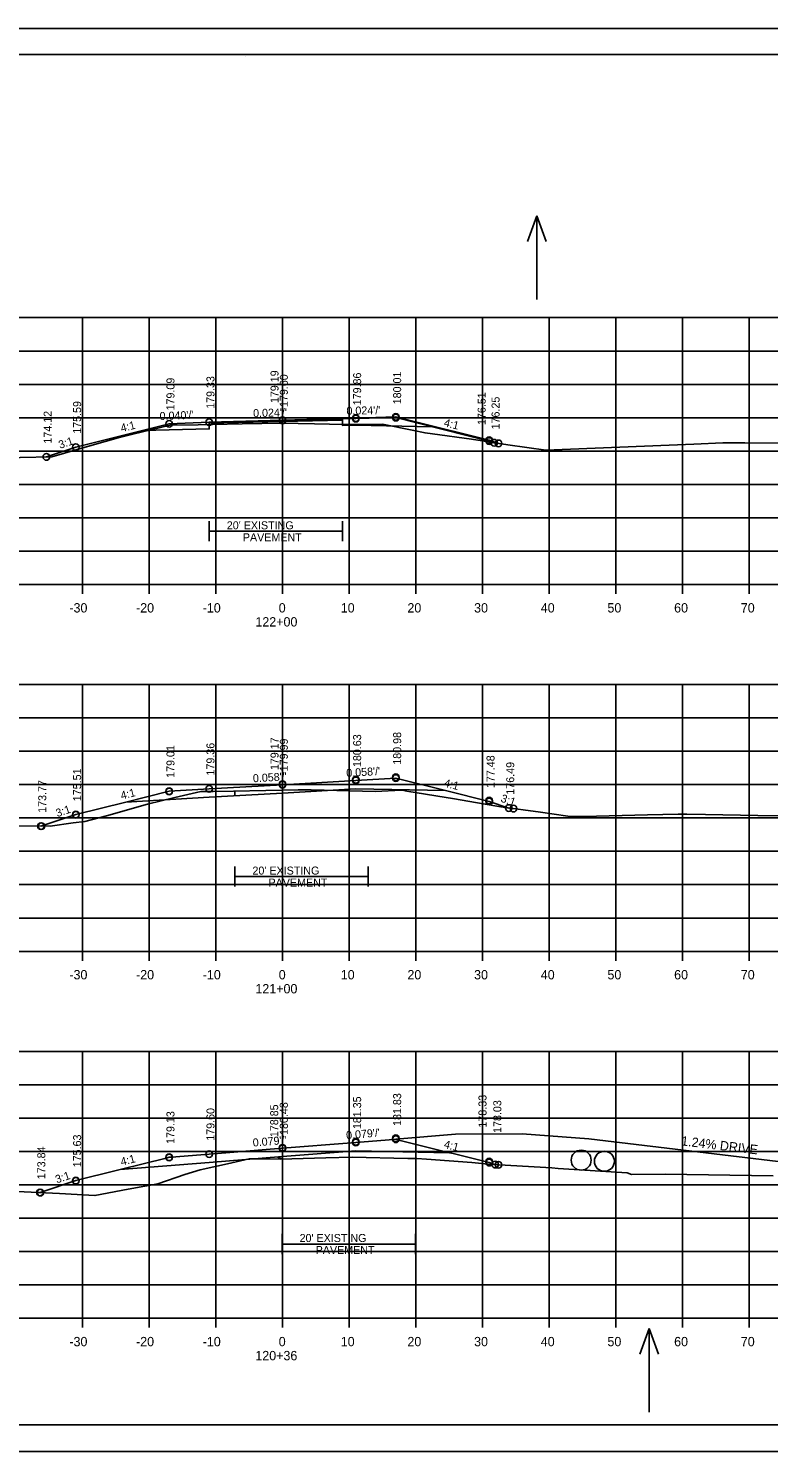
# Model space of a CAD drawing. Extents: x 915787 to 919910, y 133456 to 136717.
# Drawn here: x 916375.9 to 916486.9, y 136016.1 to 136229.4 of the extents above; entities that cross this region are included whole.
import ezdxf

# ---------------------------------------------------------------- set-up
doc = ezdxf.new("R2010")
doc.units = 0
for name, color, linetype in [('R_Alt Surface', 7, 'Continuous'), ('R_Axis', 7, 'Continuous'), ('R_Axis Annot', 7, 'Continuous'), ('R_Border', 7, 'Continuous'), ('R_Drive', 7, 'Continuous'), ('R_Exist Surface', 7, 'Continuous'), ('R_Exist Surface Annot', 7, 'Continuous'), ('R_Fin Surface', 7, 'Continuous'), ('R_Grid', 7, 'Continuous'), ('R_No Plot', 7, 'Continuous'), ('R_Water', 7, 'Continuous'), ('R_Water Annot', 7, 'Continuous'), ('R_Xsect Elev', 7, 'Continuous'), ('R_Xsect Slope', 7, 'Continuous')]:
    doc.layers.add(name, color=color, linetype=linetype)

msp = doc.modelspace()

# ---------------------------------------------------------------- linework, layer by layer
at = {"layer": 'R_Alt Surface'}
msp.add_lwpolyline([(916378.56, 136165.19), (916382.97, 136166.66), (916396.18, 136169.96), (916396.97, 136170.16), (916402.97, 136170.4), (916413.97, 136170.71), (916424.97, 136171.02), (916430.97, 136171.19), (916433.72, 136170.51), (916444.97, 136167.69), (916446.37, 136167.23)], dxfattribs=at)
at = {"layer": 'R_Axis'}
for p, q in [((916273.98, 136146.07), (916553.98, 136146.07)), ((916383.98, 136144.67), (916383.98, 136146.07)), ((916393.98, 136144.67), (916393.98, 136146.07)), ((916403.98, 136144.67), (916403.98, 136146.07)), ((916413.98, 136144.67), (916413.98, 136146.07)), ((916423.98, 136144.67), (916423.98, 136146.07)), ((916433.98, 136144.67), (916433.98, 136146.07)), ((916443.98, 136144.67), (916443.98, 136146.07)), ((916453.98, 136144.67), (916453.98, 136146.07)), ((916463.98, 136144.67), (916463.98, 136146.07)), ((916473.98, 136144.67), (916473.98, 136146.07)), ((916483.98, 136144.67), (916483.98, 136146.07)), ((916273.98, 136091.07), (916553.98, 136091.07)), ((916383.98, 136089.67), (916383.98, 136091.07)), ((916393.98, 136089.67), (916393.98, 136091.07)), ((916403.98, 136089.67), (916403.98, 136091.07)), ((916413.98, 136089.67), (916413.98, 136091.07)), ((916423.98, 136089.67), (916423.98, 136091.07)), ((916433.98, 136089.67), (916433.98, 136091.07)), ((916443.98, 136089.67), (916443.98, 136091.07)), ((916453.98, 136089.67), (916453.98, 136091.07)), ((916463.98, 136089.67), (916463.98, 136091.07)), ((916473.98, 136089.67), (916473.98, 136091.07)), ((916483.98, 136089.67), (916483.98, 136091.07)), ((916273.98, 136036.07), (916553.98, 136036.07)), ((916383.98, 136034.67), (916383.98, 136036.07)), ((916393.98, 136034.67), (916393.98, 136036.07)), ((916403.98, 136034.67), (916403.98, 136036.07)), ((916413.98, 136034.67), (916413.98, 136036.07)), ((916423.98, 136034.67), (916423.98, 136036.07)), ((916433.98, 136034.67), (916433.98, 136036.07)), ((916443.98, 136034.67), (916443.98, 136036.07)), ((916453.98, 136034.67), (916453.98, 136036.07)), ((916463.98, 136034.67), (916463.98, 136036.07)), ((916473.98, 136034.67), (916473.98, 136036.07)), ((916483.98, 136034.67), (916483.98, 136036.07))]:
    msp.add_line(p, q, dxfattribs=at)
at = {"layer": 'R_Border'}
for p, q in [((916255.98, 136225.53), (916572.16, 136225.53)), ((916408.5, 136225.27), (916408.5, 136225.27)), ((916408.5, 136225.27), (916408.5, 136225.27)), ((916572.16, 136020.07), (916255.98, 136020.07))]:
    msp.add_line(p, q, dxfattribs=at)
at = {"layer": 'R_Drive'}
for p, q in [((916406.83, 136114.4), (916406.83, 136115.08)), ((916439.94, 136063.66), (916430.97, 136062.9)), ((916449.94, 136063.71), (916439.94, 136063.66)), ((916459.91, 136062.96), (916449.94, 136063.71)), ((916459.91, 136062.96), (916508.48, 136057.13)), ((916413.26, 136060.24), (916413.9, 136059.92))]:
    msp.add_line(p, q, dxfattribs=at)
at = {"layer": 'R_Exist Surface'}
for points in [[(916365.06, 136164.93), (916379.38, 136165.2), (916385.41, 136166.96), (916389.32, 136168.07), (916391.55, 136168.62), (916397.15, 136169.96), (916401.32, 136170.02), (916403.46, 136170.05), (916407.94, 136170.15), (916413.87, 136170.27), (916418.78, 136170.15), (916423.27, 136170.04), (916426.62, 136170.06), (916428.96, 136170.09), (916433.41, 136169.19), (916435.37, 136168.79), (916436.47, 136168.66), (916442.32, 136167.85), (916447.77, 136167.01), (916453.45, 136166.19), (916475.67, 136167.12), (916479.99, 136167.31), (916483.32, 136167.3), (916499.92, 136167.25)], [(916371.67, 136109.9), (916379.14, 136109.82), (916382.56, 136110.32), (916384.35, 136110.53), (916387.56, 136111.4), (916393.73, 136113.16), (916397.84, 136114.13), (916401.74, 136115.03), (916403.6, 136115.05), (916406.65, 136115.08), (916416.3, 136115.29), (916417.35, 136115.31), (916418.27, 136115.29), (916427.91, 136115.02), (916431.77, 136115.22), (916431.92, 136115.22), (916432.64, 136115.11), (916439.77, 136113.95), (916444.09, 136113.2), (916446.74, 136112.72), (916452.69, 136111.92), (916456.77, 136111.33), (916459.17, 136111.31), (916468.71, 136111.53), (916473.31, 136111.64), (916474.62, 136111.62), (916477.43, 136111.6), (916485.28, 136111.43), (916492.58, 136111.37)], [(916373.11, 136055.1), (916380.52, 136054.78), (916385.84, 136054.46), (916390.82, 136055.41), (916395.26, 136056.22), (916399.35, 136057.6), (916401.62, 136058.33), (916405.73, 136059.24), (916409, 136059.96), (916409.9, 136059.95), (916413.69, 136059.91), (916420.46, 136060.12), (916424.43, 136060.23), (916432.75, 136060.04), (916433.95, 136060), (916433.96, 136060.01), (916433.97, 136060.01), (916434.14, 136060.03), (916435.57, 136059.92), (916442.36, 136059.4), (916444.82, 136059.15), (916446.48, 136059.08), (916454.37, 136058.61), (916455.32, 136058.53), (916465.67, 136057.86), (916466.31, 136057.64), (916471.38, 136057.66), (916487.55, 136057.42)]]:
    msp.add_lwpolyline(points, dxfattribs=at)
at = {"layer": 'R_Exist Surface Annot'}
for p, q in [((916402.98, 136155.54), (916402.98, 136152.54)), ((916422.98, 136155.54), (916422.98, 136152.54)), ((916402.98, 136154.04), (916422.98, 136154.04)), ((916406.83, 136103.78), (916406.83, 136100.78)), ((916426.83, 136103.78), (916426.83, 136100.78)), ((916406.83, 136102.28), (916426.83, 136102.28)), ((916413.9, 136048.7), (916413.9, 136045.7)), ((916433.9, 136048.7), (916433.9, 136045.7)), ((916413.9, 136047.2), (916433.9, 136047.2))]:
    msp.add_line(p, q, dxfattribs=at)
at = {"layer": 'R_Fin Surface'}
for points in [[(916378.56, 136165.19), (916382.97, 136166.66), (916392.98, 136169.16), (916396.97, 136170.16), (916402.97, 136170.4), (916413.97, 136170.67), (916424.97, 136170.93), (916430.97, 136171.08), (916444.97, 136167.58), (916445.73, 136167.32)], [(916392.98, 136169.16), (916402.98, 136169.4), (916402.97, 136170.23), (916413.97, 136170.5), (916422.97, 136170.72), (916422.98, 136169.88), (916424.98, 136169.93), (916436.47, 136169.7)], [(916377.74, 136109.84), (916382.97, 136111.58), (916390.47, 136113.45), (916396.97, 136115.08), (916402.97, 136115.43), (916413.97, 136116.06), (916424.97, 136116.7), (916430.97, 136117.05), (916438.44, 136115.18), (916444.97, 136113.55), (916447.93, 136112.56)], [(916390.47, 136113.45), (916402.97, 136114.18), (916413.97, 136114.81), (916424.97, 136115.45), (916438.44, 136115.18)], [(916377.6, 136054.91), (916377.93, 136055.02), (916382.97, 136056.7), (916389.24, 136058.27), (916389.65, 136058.37), (916396.54, 136060.09), (916396.97, 136060.2), (916397.33, 136060.23), (916402.97, 136060.68), (916403.62, 136060.73), (916413.97, 136061.55), (916424.31, 136062.37), (916424.97, 136062.42), (916430.62, 136062.87), (916430.97, 136062.9), (916431.44, 136062.78), (916439, 136060.89), (916439.36, 136060.8), (916444.97, 136059.4), (916445.77, 136059.13), (916445.86, 136059.1)], [(916389.65, 136058.37), (916402.97, 136059.43), (916413.97, 136060.3), (916424.97, 136061.17), (916439, 136060.89)]]:
    msp.add_lwpolyline(points, dxfattribs=at)
at = {"layer": 'R_Grid'}
for p, q in [((916273.98, 136186.07), (916553.98, 136186.07)), ((916383.98, 136146.07), (916383.98, 136186.07)), ((916393.98, 136146.07), (916393.98, 136186.07)), ((916403.98, 136146.07), (916403.98, 136186.07)), ((916413.98, 136146.07), (916413.98, 136186.07)), ((916423.98, 136146.07), (916423.98, 136186.07)), ((916433.98, 136146.07), (916433.98, 136186.07)), ((916443.98, 136146.07), (916443.98, 136186.07)), ((916453.98, 136146.07), (916453.98, 136186.07)), ((916463.98, 136146.07), (916463.98, 136186.07)), ((916473.98, 136146.07), (916473.98, 136186.07)), ((916483.98, 136146.07), (916483.98, 136186.07)), ((916273.98, 136181.07), (916553.98, 136181.07)), ((916273.98, 136176.07), (916553.98, 136176.07)), ((916273.98, 136171.07), (916553.98, 136171.07)), ((916273.98, 136166.07), (916553.98, 136166.07)), ((916273.98, 136161.07), (916553.98, 136161.07)), ((916273.98, 136156.07), (916553.98, 136156.07)), ((916273.98, 136151.07), (916553.98, 136151.07)), ((916273.98, 136146.07), (916553.98, 136146.07)), ((916273.98, 136131.07), (916553.98, 136131.07)), ((916383.98, 136091.07), (916383.98, 136131.07)), ((916393.98, 136091.07), (916393.98, 136131.07)), ((916403.98, 136091.07), (916403.98, 136131.07)), ((916413.98, 136091.07), (916413.98, 136131.07)), ((916423.98, 136091.07), (916423.98, 136131.07)), ((916433.98, 136091.07), (916433.98, 136131.07)), ((916443.98, 136091.07), (916443.98, 136131.07)), ((916453.98, 136091.07), (916453.98, 136131.07)), ((916463.98, 136091.07), (916463.98, 136131.07)), ((916473.98, 136091.07), (916473.98, 136131.07)), ((916483.98, 136091.07), (916483.98, 136131.07)), ((916273.98, 136126.07), (916553.98, 136126.07)), ((916273.98, 136121.07), (916553.98, 136121.07)), ((916273.98, 136116.07), (916553.98, 136116.07)), ((916273.98, 136111.07), (916553.98, 136111.07)), ((916273.98, 136106.07), (916553.98, 136106.07)), ((916273.98, 136101.07), (916553.98, 136101.07)), ((916273.98, 136096.07), (916553.98, 136096.07)), ((916273.98, 136091.07), (916553.98, 136091.07)), ((916273.98, 136076.07), (916553.98, 136076.07)), ((916383.98, 136036.07), (916383.98, 136076.07)), ((916393.98, 136036.07), (916393.98, 136076.07)), ((916403.98, 136036.07), (916403.98, 136076.07)), ((916413.98, 136036.07), (916413.98, 136076.07)), ((916423.98, 136036.07), (916423.98, 136076.07)), ((916433.98, 136036.07), (916433.98, 136076.07)), ((916443.98, 136036.07), (916443.98, 136076.07)), ((916453.98, 136036.07), (916453.98, 136076.07)), ((916463.98, 136036.07), (916463.98, 136076.07)), ((916473.98, 136036.07), (916473.98, 136076.07)), ((916483.98, 136036.07), (916483.98, 136076.07)), ((916273.98, 136071.07), (916553.98, 136071.07)), ((916273.98, 136066.07), (916553.98, 136066.07)), ((916273.98, 136061.07), (916553.98, 136061.07)), ((916273.98, 136056.07), (916553.98, 136056.07)), ((916273.98, 136051.07), (916553.98, 136051.07)), ((916273.98, 136046.07), (916553.98, 136046.07)), ((916273.98, 136041.07), (916553.98, 136041.07)), ((916273.98, 136036.07), (916553.98, 136036.07))]:
    msp.add_line(p, q, dxfattribs=at)
at = {"layer": 'R_No Plot'}
for p, q in [((916243.57, 136229.43), (916576.91, 136229.43)), ((916243.57, 136016.09), (916576.91, 136016.09))]:
    msp.add_line(p, q, dxfattribs=at)
for points in [[(916243.57, 136229.43), (916576.91, 136229.43), (916576.91, 136016.09), (916243.57, 136016.09)], [(916489.9, 136225.53), (916489.9, 136215.65), (916525.63, 136215.65), (916525.63, 136212.73), (916548.83, 136212.73), (916548.83, 136189.52), (916572.16, 136189.52), (916572.16, 136020.07), (916255.98, 136020.07), (916255.98, 136225.53)]]:
    msp.add_lwpolyline(points, close=True, dxfattribs=at)
for centre in [(916424.97, 136171.02), (916424.97, 136170.93), (916430.97, 136171.19), (916430.97, 136171.08), (916396.97, 136170.16), (916396.97, 136170.16), (916402.97, 136170.4), (916402.97, 136170.4), (916413.97, 136170.71), (916413.97, 136170.67), (916382.97, 136166.66), (916382.97, 136166.66), (916444.97, 136167.69), (916444.97, 136167.58), (916445.73, 136167.32), (916446.37, 136167.23), (916378.56, 136165.19), (916378.56, 136165.19), (916402.97, 136115.43), (916402.97, 136115.43), (916413.97, 136116.12), (916413.97, 136116.06), (916424.97, 136116.81), (916424.97, 136116.7), (916430.97, 136117.18), (916430.97, 136117.05), (916396.97, 136115.08), (916396.97, 136115.05), (916444.97, 136113.68), (916444.97, 136113.55), (916382.97, 136111.58), (916382.97, 136111.55), (916447.93, 136112.56), (916448.61, 136112.47), (916377.74, 136109.84), (916377.83, 136109.84), (916424.97, 136062.54), (916424.97, 136062.42), (916430.97, 136063.05), (916430.97, 136062.9), (916396.97, 136060.2), (916396.97, 136060.17), (916402.97, 136060.68), (916402.97, 136060.68), (916413.97, 136061.61), (916413.97, 136061.55), (916444.97, 136059.55), (916444.97, 136059.4), (916445.86, 136059.1), (916446.37, 136059.08), (916382.97, 136056.7), (916382.97, 136056.67), (916377.6, 136054.91), (916377.69, 136054.9)]:
    msp.add_circle(centre, 0.5, dxfattribs=at)
at = {"layer": 'R_Water'}
for centre in [(916458.77, 136059.77), (916462.25, 136059.6)]:
    msp.add_circle(centre, 1.5, dxfattribs=at)
at = {"layer": 'R_Water Annot'}
for p, q in [((916452.1, 136201.33), (916450.7, 136197.49)), ((916452.1, 136188.77), (916452.1, 136201.33)), ((916452.1, 136201.33), (916453.5, 136197.49)), ((916468.95, 136034.54), (916467.55, 136030.7)), ((916468.95, 136021.97), (916468.95, 136034.54)), ((916468.95, 136034.54), (916470.35, 136030.7))]:
    msp.add_line(p, q, dxfattribs=at)

# ---------------------------------------------------------------- texts
at = {"layer": 'R_Axis Annot'}
for s, p in [('-30', (916382.01, 136141.87)), ('-20', (916392.01, 136141.87)), ('-10', (916402.01, 136141.87)), ('0', (916413.41, 136141.87)), ('10', (916422.71, 136141.87)), ('20', (916432.71, 136141.87)), ('30', (916442.71, 136141.87)), ('40', (916452.71, 136141.87)), ('50', (916462.71, 136141.87)), ('60', (916472.71, 136141.87)), ('70', (916482.71, 136141.87)), ('122+00', (916409.91, 136139.77)), ('-30', (916382.01, 136086.87)), ('-20', (916392.01, 136086.87)), ('-10', (916402.01, 136086.87)), ('0', (916413.41, 136086.87)), ('10', (916422.71, 136086.87)), ('20', (916432.71, 136086.87)), ('30', (916442.71, 136086.87)), ('40', (916452.71, 136086.87)), ('50', (916462.71, 136086.87)), ('60', (916472.71, 136086.87)), ('70', (916482.71, 136086.87)), ('121+00', (916409.91, 136084.77)), ('-30', (916382.01, 136031.87)), ('-20', (916392.01, 136031.87)), ('-10', (916402.01, 136031.87)), ('0', (916413.41, 136031.87)), ('10', (916422.71, 136031.87)), ('20', (916432.71, 136031.87)), ('30', (916442.71, 136031.87)), ('40', (916452.71, 136031.87)), ('50', (916462.71, 136031.87)), ('60', (916472.71, 136031.87)), ('70', (916482.71, 136031.87)), ('120+36', (916409.9, 136029.77))]:
    msp.add_text(s, height=1.4, dxfattribs=at).set_placement(p)
at = {"layer": 'R_Drive'}
msp.add_text('1.24% DRIVE', height=1.4, rotation=353.1572, dxfattribs=at).set_placement((916473.72, 136062))
at = {"layer": 'R_Exist Surface Annot'}
for s, p in [("20' EXISTING", (916405.62, 136154.34)), ('PAVEMENT', (916408.03, 136152.54)), ("20' EXISTING", (916409.47, 136102.58)), ('PAVEMENT', (916411.88, 136100.78)), ("20' EXISTING", (916416.54, 136047.5)), ('PAVEMENT', (916418.95, 136045.7))]:
    msp.add_text(s, height=1.2, dxfattribs=at).set_placement(p)
at = {"layer": 'R_Xsect Elev'}
for s, p in [('179.19', (916413.38, 136173.26)), ('179.86', (916425.77, 136172.93)), ('180.01', (916431.77, 136173.08)), ('179.09', (916397.77, 136172.16)), ('179.33', (916403.77, 136172.4)), ('179.60', (916414.77, 136172.67)), ('175.59', (916383.77, 136168.66)), ('176.51', (916444.44, 136169.98)), ('176.25', (916446.53, 136169.32)), ('174.12', (916379.36, 136167.19)), ('179.36', (916403.77, 136117.43)), ('179.17', (916413.38, 136118.24)), ('179.99', (916414.77, 136118.06)), ('180.63', (916425.77, 136118.7)), ('180.98', (916431.77, 136119.05)), ('179.01', (916397.77, 136117.08)), ('177.48', (916445.77, 136115.55)), ('175.51', (916383.77, 136113.58)), ('176.49', (916448.73, 136114.56)), ('173.77', (916378.54, 136111.84)), ('181.35', (916425.77, 136064.42)), ('181.83', (916431.77, 136064.9)), ('178.33', (916444.57, 136064.65)), ('179.13', (916397.77, 136062.2)), ('179.60', (916403.77, 136062.68)), ('178.85', (916413.33, 136063.22)), ('180.48', (916414.77, 136063.55)), ('178.03', (916446.79, 136063.85)), ('175.63', (916383.77, 136058.7)), ('173.84', (916378.4, 136056.91))]:
    msp.add_text(s, height=1.2, rotation=90, dxfattribs=at).set_placement(p)
at = {"layer": 'R_Xsect Slope'}
for s, rotation, p in [("0.040'/'", 2.2906, (916395.57, 136170.71)), ("0.024'/'", 1.3834, (916409.58, 136171.16)), ("0.024'/'", 1.3834, (916423.58, 136171.5)), ('4:1', 14.0362, (916389.85, 136168.9)), ('4:1', 345.9638, (916438.1, 136169.81)), ('3:1', 18.4349, (916380.61, 136166.4)), ("0.058'/'", 3.3109, (916409.57, 136116.41)), ("0.058'/'", 3.3109, (916423.57, 136117.22)), ('4:1', 345.9638, (916438.1, 136115.78)), ('4:1', 14.0362, (916389.85, 136113.82)), ('3:1', 341.5651, (916446.61, 136113.53)), ('3:1', 18.4349, (916380.2, 136111.18)), ("0.079'/'", 4.5409, (916409.56, 136061.8)), ("0.079'/'", 4.5409, (916423.56, 136062.91)), ('4:1', 345.9637, (916438.1, 136061.63)), ('4:1', 14.0363, (916389.85, 136058.93)), ('3:1', 18.435, (916380.13, 136056.28))]:
    msp.add_text(s, height=1.2, rotation=rotation, dxfattribs=at).set_placement(p)

doc.saveas('drawing.dxf')
